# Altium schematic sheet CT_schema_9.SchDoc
size 391 x 238 mm
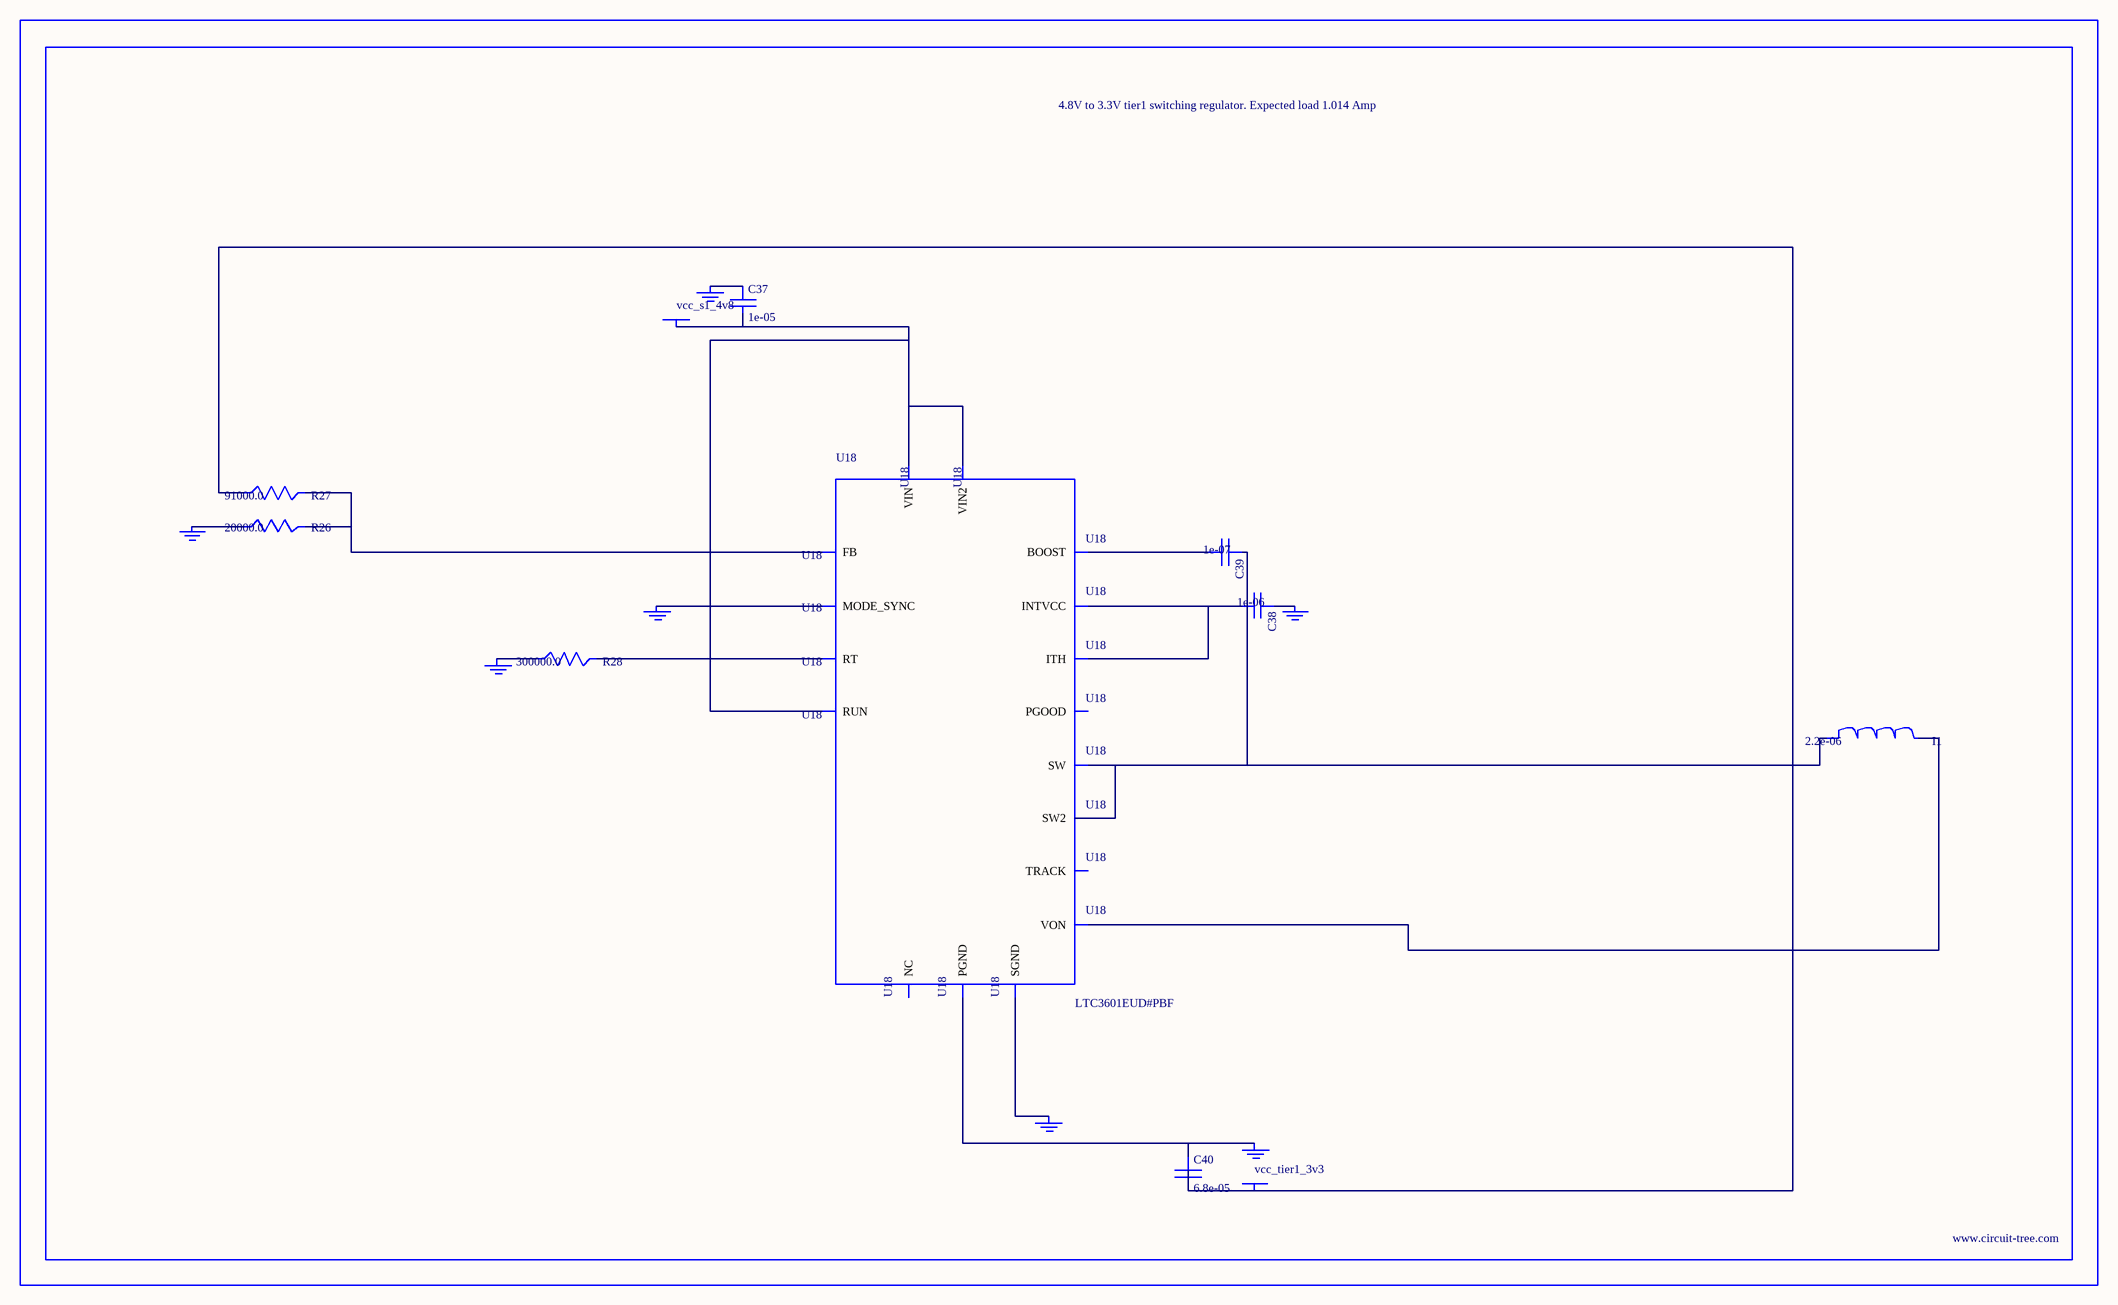
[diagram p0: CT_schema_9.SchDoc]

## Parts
BORDER8  (no value)
C37  1e-05  [C0805]
C38  1e-06  [C0603]
C39  1e-07  [C0402]
C40  6.8e-05  [2220]
GND_INSTANCE_8_0  (no value)
GND_INSTANCE_8_1  (no value)
GND_INSTANCE_8_2  (no value)
GND_INSTANCE_8_3  (no value)
GND_INSTANCE_8_4  (no value)
GND_INSTANCE_8_5  (no value)
GND_INSTANCE_8_6  (no value)
I1  2.2e-06  [IND_PM3316]
POWER_INSTANCE_8_0  vcc_s1_4v8
POWER_INSTANCE_8_1  vcc_tier1_3v3
R26  20000.0  [R0603]
R27  91000.0  [R0603]
R28  300000.0  [R0603]
U18  LTC3601EUD#PBF  [QFN-16_EP]

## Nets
NetC37_1: C37.1 GND_INSTANCE_8_5.0(GND)
NetC37_2: C37.2 POWER_INSTANCE_8_0.0(PWR) U18.14(RUN) U18.15(VIN) U18.16(VIN2)
NetC38_1: C38.1 GND_INSTANCE_8_1.0(GND)
NetC38_2: C38.2 U18.7(INTVCC) U18.12(ITH)
NetC39_1: C39.1 I1.1 U18.3(SW) U18.4(SW2)
NetC39_2: C39.2 U18.6(BOOST)
NetC40_1: C40.1 GND_INSTANCE_8_6.0(GND) U18.17(PGND)
NetC40_2: C40.2 I1.2 POWER_INSTANCE_8_1.0(PWR) R27.1 U18.8(VON)
NetGND_INSTANCE_8_0_0: GND_INSTANCE_8_0.0(GND) U18.1(MODE_SYNC)
NetGND_INSTANCE_8_2_0: GND_INSTANCE_8_2.0(GND) U18.9(SGND)
NetGND_INSTANCE_8_3_0: GND_INSTANCE_8_3.0(GND) R28.1
NetGND_INSTANCE_8_4_0: GND_INSTANCE_8_4.0(GND) R26.1
NetR26_2: R26.2 R27.2 U18.11(FB)
NetR28_2: R28.2 U18.10(RT)

Not connected (* = marked no-connect by the designer): U18 2(PGOOD) 5(NC) 13(TRACK)

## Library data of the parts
BORDER8 = BORDER_PAGE8
C37 = C0805C106K8RACTU
C38 = C0603C105K3RACTU
C39 = C0402C104K3RACTU
C40 = C5750X5R1A686M
GND_INSTANCE_8_0-GND_INSTANCE_8_6 = GND
I1 = PM3316-2R2M-RC
POWER_INSTANCE_8_0 POWER_INSTANCE_8_1 = PWR
R26 = RC0603JR-0720KL
R27 = RC0603JR-0791KL
R28 = RC0603JR-07300KL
